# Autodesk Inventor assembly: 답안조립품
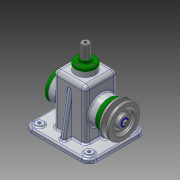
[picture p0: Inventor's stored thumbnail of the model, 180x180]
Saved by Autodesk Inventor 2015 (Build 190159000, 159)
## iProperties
Created: 2016-02
Part Number: 답안조립품
Document SubType Name: Assembly
Designer: Administrator
Author: Administrator
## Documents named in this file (19)
- C:\Users\Administrator\Desktop\460219V1014\답안조립품.iam
- C:\Users\Administrator\Desktop\460219V1014\본체.ipt
- C:\Users\Administrator\Desktop\460219V1014\V-벨트풀리.ipt
- C:\Users\Administrator\Desktop\460219V1014\고정핀.ipt
- C:\Users\Administrator\Desktop\460219V1014\뒤커버.ipt
- C:\Users\Administrator\Desktop\460219V1014\링크.ipt
- C:\Users\Administrator\Desktop\460219V1014\멈춤링 6 x 5.ipt
- C:\Users\Administrator\Desktop\460219V1014\멈춤링 15 x 1.ipt
- C:\Users\Administrator\Desktop\460219V1014\베어링 15 x 35 x 11.ipt
- C:\Users\Administrator\Desktop\460219V1014\볼트 M3 x 8.ipt
- C:\Users\Administrator\Desktop\460219V1014\볼트 M4 x 10.ipt
- C:\Users\Administrator\Desktop\460219V1014\볼트 M6 x 12.ipt
- C:\Users\Administrator\Desktop\460219V1014\상부부시.ipt
- C:\Users\Administrator\Desktop\460219V1014\슬라이드바.ipt
- C:\Users\Administrator\Desktop\460219V1014\앞커버.ipt
- C:\Users\Administrator\Desktop\460219V1014\오일실 15 25 7.ipt
- C:\Users\Administrator\Desktop\460219V1014\와셔.ipt
- C:\Users\Administrator\Desktop\460219V1014\키 5 x 5 x 14.ipt
- C:\Users\Administrator\Desktop\460219V1014\편심축.ipt
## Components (15 placed, 5 different names)
1. V-벨트풀리:1
2. 고정핀:1
3. ISO 4018 M6 x 12:1
4. ISO 4762 M3 x 8:1
5. ISO 4762 M3 x 8:2
6. ISO 4762 M3 x 8:3
7. ISO 4762 M3 x 8:4
8. ISO 4762 M4 x 10:1
9. ISO 4762 M4 x 10:2
10. ISO 4762 M4 x 10:3
11. ISO 4762 M4 x 10:4
12. ISO 4762 M4 x 10:5
13. ISO 4762 M4 x 10:6
14. ISO 4762 M4 x 10:7
15. ISO 4762 M4 x 10:8
